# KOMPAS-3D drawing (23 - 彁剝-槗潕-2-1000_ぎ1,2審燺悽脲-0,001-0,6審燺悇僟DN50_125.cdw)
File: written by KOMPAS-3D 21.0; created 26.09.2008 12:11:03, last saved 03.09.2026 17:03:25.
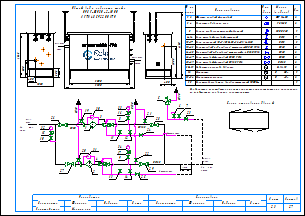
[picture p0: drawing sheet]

Sheets 1-2: A3, landscape

Document properties: Наименование: Макро:21; Автор: RaskoAdmin; Форматы листов документа: 2xA3; Полное имя файла: \\UR38nt01\Departments\КТО\КБ ПУРДГ\Заявки\Прайс-лист на типовые шкафы ГРПШ\ПРДГ_стандарт_20_03_2026\ПРДГ с РДГ(Н, В)\ПРДГ-ШУЭО-2-1000_до1,2МПа_Рвых-0,001-0,6МПа_РДГ_DN50_125.cdw

Title block, sheet 1: Наименование: Пункт учета газа / ПУГ-Ш-400-Р / ЛГТИ.485922.001ТУ; designation: ЛГТИ.03.4411141; sheet number: 1; Количество листов документа: 2; organisation: ООО "ЭЛЬСТЕР Газэлектроника"; Форматы листов документа: A3; stored path: C:\Рабочие документы\Компас\ПУГ\Схема.cdw; Разработал: Устинов; Проверил: Кошкин; Утвердил: Кошкин
Title block, sheet 2: sheet number: 2; stored path: D:\Рабочие документы\Заявки\ПУРДГ\ПУРДГ-ШУЭО-2-100-Р 4411220.cdw; designation, second copy: ЛГТИ.03.4411141-

Views: Вид 1, Вид 2
Referenced files: wcvoit.frw
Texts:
  Normal
  № на
  схеме
  Усл.
  обозн.
  Марка
  (модель)
  Кол.
  Фильтр газовый фланцевый
  ФГ 16-50
  Регулятор давления газа
  РДГ-50
  Клапан предохранительный сбросной
  КПС DN20
  Кран шаровой газовый латунный
  DN15
  Кран кнопочный VE-РАСКО-НЗ-1,6-G1/2-М20
  Кран шаровой "под приварку" штуцерный DN20 PN16
  Кран шаровой "под приварку" штуцерный п/п DN20 PN16
  DN20
  Кран шаровой фланцевый DN50 PN16
  Кран шаровой фланцевый DN125 PN16
  DN50
  DN125
  Индикатор перепада давления
  Delta 15
  Манометр
  Манометр-напоромер
  Электрообогреватель взрывозащищенный 1000Вт
  0...     МПа
  0...     кПа
  Общий вид и габариты шкафа
  ПРДГ-ШУЭО-2-1000
  Выход газа
  Вход газа
  logo-rasko-ge.png
  Вход
  газа
  PDI
  Выход
  Р=     кПа
  Импульс DN20
  ≥5DN
  HYSWLongFangSong
  Р=       МПа
  Схема открывания дверей
  Предприятие изготовитель может заменять комплектующие на аналогичные,
  не ухудшающие заявленных характеристик.
  Должность
  Конструктор
  Фамилия
  Подпись
  Дата
  Согласовано
  Максимкин
  Лист
  Листов
  POLYLINE_STYLE_0.18_RGB_0_0_0
  POLYLINE_STYLE_0.50_RGB_0_0_0
  POLYLINE_STYLE_0.34_RGB_0_0_0
  PHANTOM_RGB_0_0_0_SC_1_THICK_0.18
  K5LT_THIN_RGB_0_0_0_THICK_0.18
  K5LT32769_RGB_0_0_0_THICK_0.18
  K5LT12_RGB_0_0_0_SC_1_THICK_0.18
  K5LT_DASHED_RGB_0_0_0_SC_1_THICK_0.18
  ACISOTGL_RGB_0_0_0_SC_0.8_THICK_0.25
  CONTINUOUS_RGB_0_127_31_THICK_0.3
  CONTINUOUS_RGB_0_0_255_THICK_0.35
  CONTINUOUS_RGB_255_0_0_THICK_0.35
  POLYLINE_STYLE_0.25_RGB_0_0_0
  CONTINUOUS_RGB_0_0_0_THICK_0.5
  POLYLINE_STYLE_0.35_RGB_0_0_255
  CONTINUOUS_RGB_0_0_0_THICK_0.4
  CONTINUOUS_RGB_0_0_0_THICK_0.35
  Без оформления
Dimensions and other numbers on the sheet: 1; 1, 2; 2; 3, 4; 5; 6-14; 9; 15-17; 3; 18-23; 24-25; 6; 26-27; 28-29; 30-31; 32; 33-34; 35; 400; 1050; 500; 305; 1565; 3300; 1000; 4130; 3000; 4; 10; 27; 28; 29; 23; 8; 12; 19; 20; 21; 22; 25; 24; 30; 31; 15; 16; 26; 7; 11; 14; 13; 33; 17; 34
